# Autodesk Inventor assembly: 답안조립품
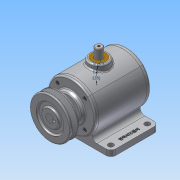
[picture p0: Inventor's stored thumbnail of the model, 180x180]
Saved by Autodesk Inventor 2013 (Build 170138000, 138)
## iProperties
Created: 2015-08
Part Number: 답안조립품
Document SubType Name: Assembly
Designer: Administrator
Mass: 1590.53 g
Surface Area: 2017.36 cm^2
Volume: 938.374 cm^3
Density: 1.69499 g/cm^3
Author: Administrator
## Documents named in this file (14)
- C:\Users\Administrator\Desktop\350806V1026\답안조립품.iam
- C:\Users\Administrator\Desktop\350806V1026\본체.ipt
- C:\Users\Administrator\Desktop\350806V1026\앞커버.ipt
- C:\Users\Administrator\Desktop\350806V1026\M4-소켓머리.ipt
- C:\Users\Administrator\Desktop\350806V1026\오일실.ipt
- C:\Users\Administrator\Desktop\350806V1026\베어링 6203.ipt
- C:\Users\Administrator\Desktop\350806V1026\뒷커버.ipt
- C:\Users\Administrator\Desktop\350806V1026\부시.ipt
- C:\Users\Administrator\Desktop\350806V1026\축.ipt
- C:\Users\Administrator\Desktop\350806V1026\KS B 1311 - 5 x 5 x 18I.ipt
- C:\Users\Administrator\Desktop\350806V1026\V-벨트풀리.ipt
- C:\Users\Administrator\Desktop\350806V1026\KS B 1028  - 납작점M4x5.ipt
- C:\Users\Administrator\Desktop\350806V1026\슬라이더.ipt
- C:\Users\Administrator\Desktop\350806V1026\13-스프링.ipt
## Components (15 placed, 7 different names)
1. 8-오일실:1
2. 7-베어링 6203:1
3. 7-베어링 6203:2
4. KS B 1311 (I) 5 x 5 x 18:1 — 각도:1, 각도:2
5. V-벨트풀리:1 — 각도:2, 플러쉬:1
6. KS B 1028 납작점 - 미터 납작점M4x5:1
7. 13-스프링:1
8. 9-M4-소켓머리:1
9. 9-M4-소켓머리:2
10. 9-M4-소켓머리:3
11. 9-M4-소켓머리:4
12. 9-M4-소켓머리:5
13. 9-M4-소켓머리:6
14. 9-M4-소켓머리:7
15. 9-M4-소켓머리:8
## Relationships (3: Angle 2, Flush 1)
- 각도:1 [Angle]: KS B 1311 (I) 5 x 5 x 18:1
- 각도:2 [Angle]: KS B 1311 (I) 5 x 5 x 18:1 ↔ V-벨트풀리:1
- 플러쉬:1 [Flush]: V-벨트풀리:1
